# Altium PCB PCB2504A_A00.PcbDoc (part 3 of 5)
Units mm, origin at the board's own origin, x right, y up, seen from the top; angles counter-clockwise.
Board outline 115 x 60 mm, 6 copper layers (Top Layer, Signal Layer 2, Signal Layer 3, Signal Layer 4, Signal Layer 5, Bottom Layer), stack 1.555 mm thick; 403 components, 294 nets, 1344 pads, 774 vias.
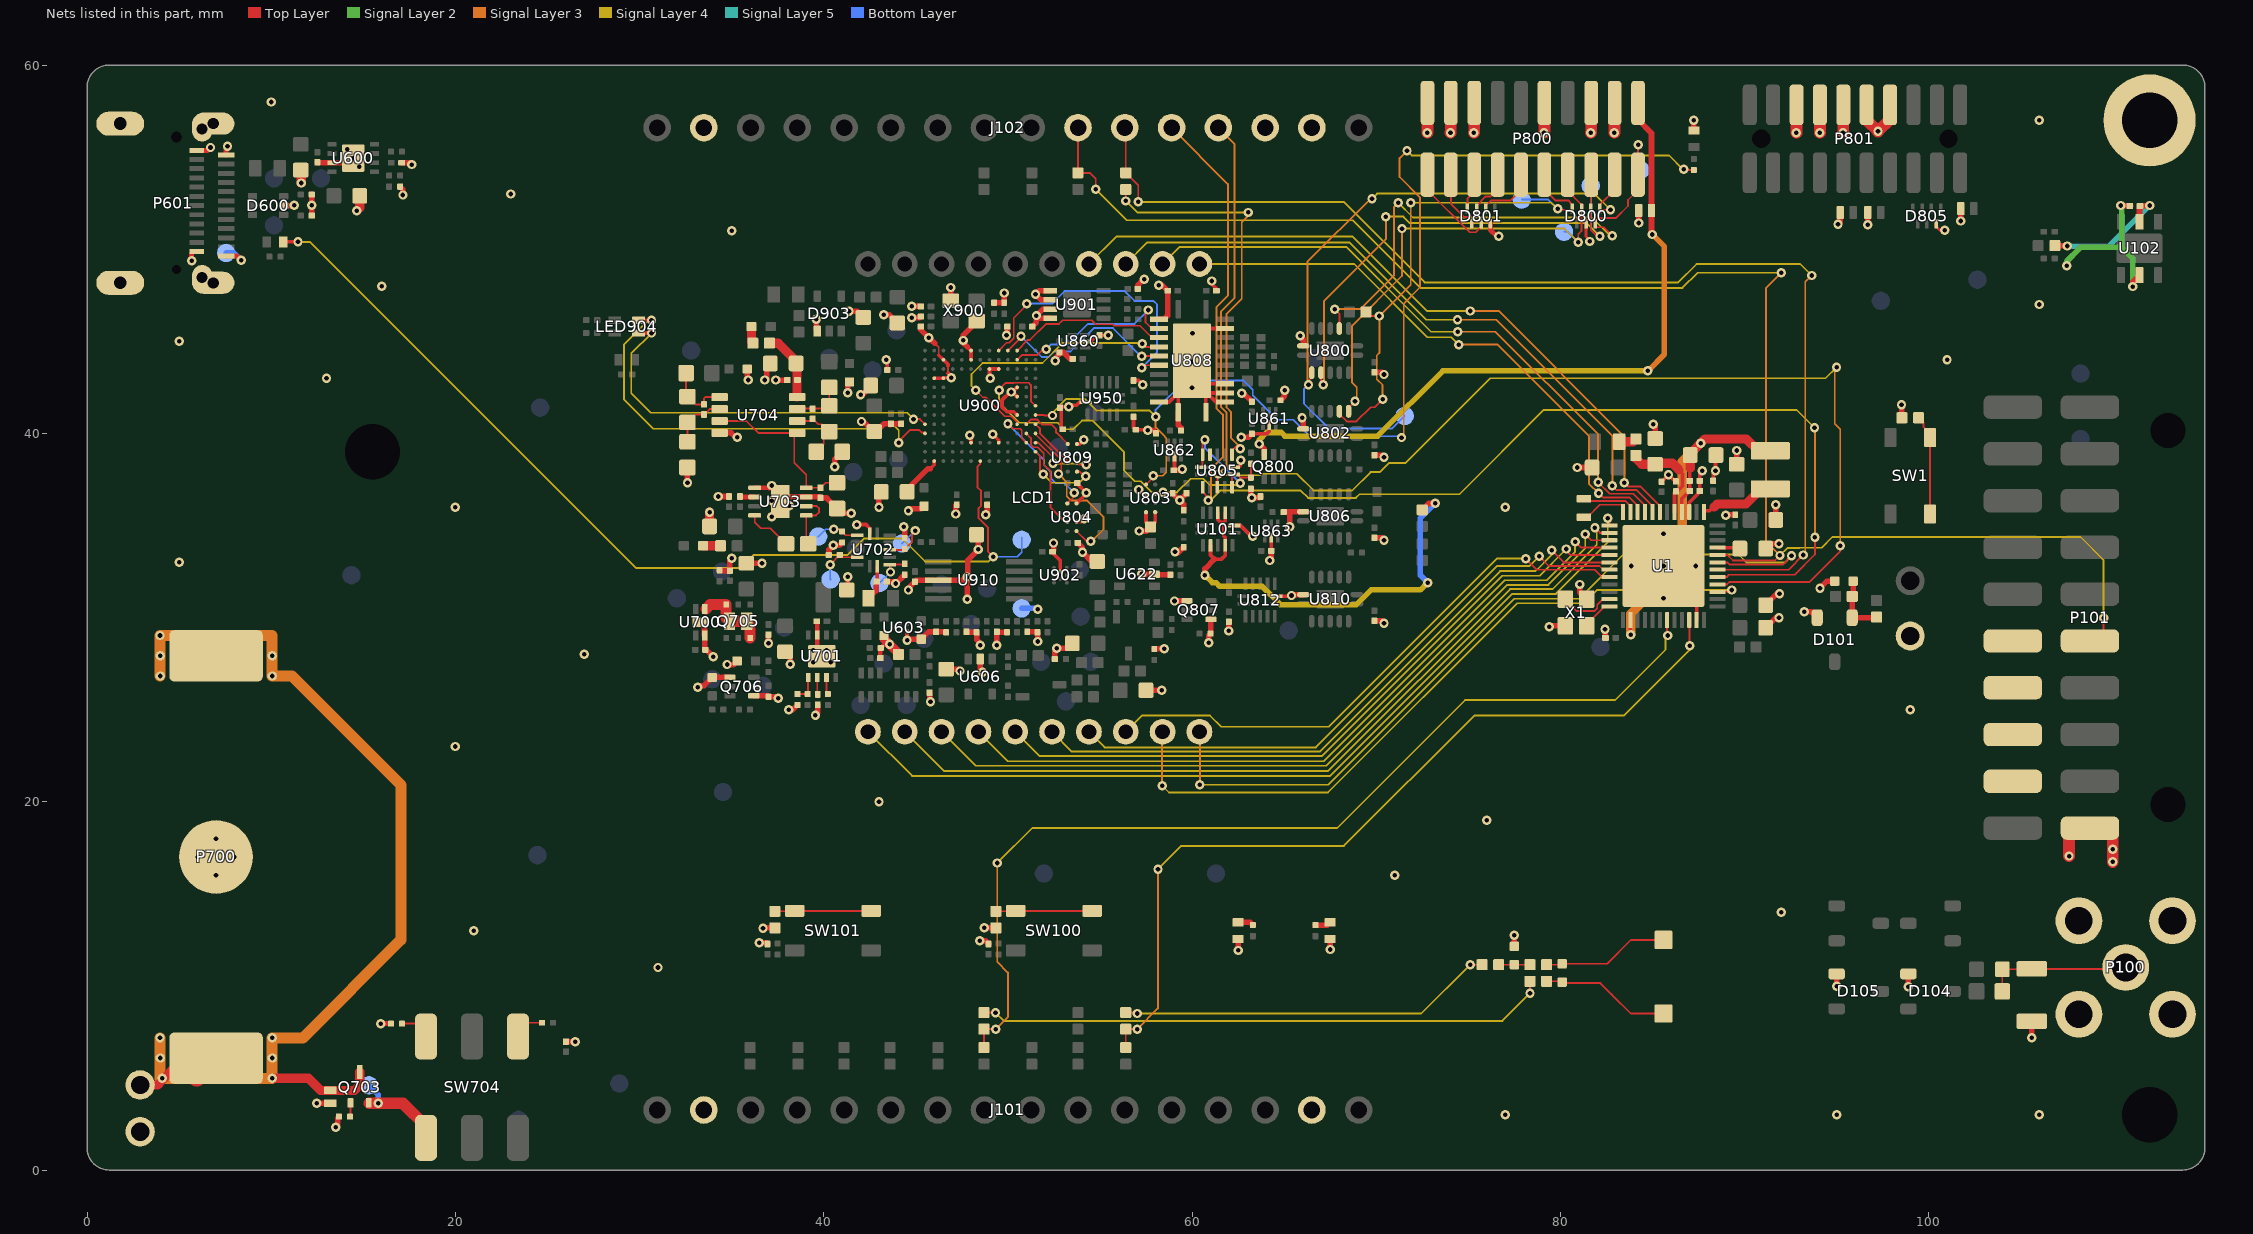
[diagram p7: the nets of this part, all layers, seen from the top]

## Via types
v1: diameter 0.508, hole 0.25, Top Layer to Bottom Layer, tented both sides, 774 vias

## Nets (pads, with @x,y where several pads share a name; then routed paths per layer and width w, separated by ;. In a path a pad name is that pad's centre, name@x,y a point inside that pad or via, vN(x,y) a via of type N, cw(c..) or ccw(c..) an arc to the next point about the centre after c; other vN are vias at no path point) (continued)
BREAKOUT_TOP10: J102.10 P101.9 R301.1 U1.32 | length 87.5
  Top Layer w0.1: J102.10@53.81,56.602 53.81,54.16 R301.1@53.8,54.15 54.45,54.15 54.775,53.825 v1(54.775,53.25) ; U1.32@88.535,33.4 89.075,33.4 89.375,33.1 91.65,33.1 v1(91.925,33.375) ; P101.9@108.76,28.73 109.205,28.73 109.5,29.025 v1(109.5,29.975)
  Signal Layer 3 w0.1: v1(91.925,33.375) 91.175,34.125 91.175,47.9 v1(92,48.725)
  Signal Layer 4 w0.1: v1@54.775,53.375 v1(54.775,53.25) 56.45,51.575 68.725,51.575 72.4,47.9 86.626,47.9 87.451,48.725 v1(92,48.725) ; v1(91.925,33.375) 92.325,33.775 92.65,33.775 ; v1(109.5,29.975) 109.5,33.125 108.25,34.375 94.775,34.375 94.193,33.793 92.993,33.793 ; 92.65,33.775 92.975,33.775 92.993,33.793 ; 92.65,33.775 92.668,33.793 92.993,33.793
BREAKOUT_TOP11: J102.11 R300.1 U1.30 | length 63.7
  Top Layer w0.1: J102.11@56.35,56.602 56.4,56.552 R300.1@56.4,54.15 57.075,53.475 v1(57.075,52.575) ; U1.30@88.535,32.6 92.4,32.6 v1(93.2,33.4)
  Signal Layer 3 w0.1: v1(93.2,33.4) 93.3,33.5 93.3,48.225 v1(93.65,48.575)
  Signal Layer 4 w0.1: v1(57.075,52.575) 68.25,52.575 72.625,48.2 86.4,48.2 87.4,49.2 93.025,49.2 v1(93.65,48.575)
BREAKOUT_TOP12: J102.12 U1.29 U805.1 | length 71.4
  Top Layer w0.1: U805.1@60.575,37.085 60.575,36.825 60.885,36.515 v1(60.885,36.379) ; U1.29@88.535,32.2 89.025,32.2 89.15,32.325 92.725,32.325 93.825,33.425 v1(93.825,34.363)
  Signal Layer 3 w0.1: J102.12@58.89,56.602 61.95,53.542 61.95,47.475 61.325,46.85 61.325,41.375 61.675,41.025 61.675,38.7 61.025,38.05 61.025,36.519 v1(60.885,36.379) ; v1(93.8,40.3) 93.825,40.275 v1(93.825,34.363)
  Signal Layer 4 w0.1: v1(60.885,36.379) 61.007,36.379 61.521,36.893 65.907,36.893 66.3,36.5 68.894,36.5 69.094,36.7 74.525,36.7 79.1,41.275 92.825,41.275 v1(93.8,40.3)
BREAKOUT_TOP13: J102.13 U1.28 U805.3 | length 75
  Top Layer w0.1: U805.3@61.375,37.085 v1@61.375,37.65 ; U1.28@88.535,31.8 89.044,31.8 89.169,31.925 93.525,31.925 95.2,33.6 v1(95.2,33.9)
  Signal Layer 3 w0.1: v1(61.425,37.8) 61.875,38.25 61.875,41.125 61.575,41.425 61.575,46.625 62.3,47.35 62.3,55.732 J102.13@61.43,56.602 ; v1(95,43.6) 95,43.7 95.1,43.7 94.9,43.5 94.9,40.525 95.2,40.225 v1(95.2,33.9)
  Signal Layer 4 w0.1: v1(61.425,37.8) 61.5,37.725 63.675,37.725 63.757,37.807 65.693,37.807 66.6,36.9 68.7,36.9 69.7,37.9 70.2,37.9 70.7,38.4 71.6,38.4 76.2,43 94.4,43 v1(95,43.6)
BREAKOUT_TOP14: J102.14
DAC_LC_EXCITE: R121.1 R304.2 | length 20.5
  Top Layer w0.1: R304.2@56.4,8.55 56.975,8.55 v1(57.025,8.5) ; v1(75.1,11.15) R121.1@75.75,11.15
  Signal Layer 4 w0.1: v1(57.025,8.5) 72.45,8.5 v1(75.1,11.15)
DBG_VREGO: C902.1 U900.A12 | length 2.4
  Top Layer w0.1: C902.1@44.45,36.875 44.5,36.825 C902.1@44.525,36.825
  Top Layer w0.2: 45.788,38.088 46,38.3 U900.A12@46,38.5
  Top Layer w0.3: C902.1@44.45,36.875 45.663,38.088 45.788,38.088
DEBUG_#RESET_IN: U808.7 U900.N5 | length 15.7
  Top Layer w0.1: U900.N5@49.5,44.5 49.925,44.925 50.081,44.925 50.318,45.162 50.318,46.268 51.025,46.975 v1(51.025,47.05) ; v1(57.275,43.575) 57.275,43.6 57.375,43.7 U808.7@58.205,43.7
  Bottom Layer w0.1: v1(51.025,47.05) 52.4,47.05 53.075,47.725 56.35,47.725 56.875,47.2 57.9,47.2 58.1,47 58.1,44.4 v1(57.275,43.575)
DEBUG_DH_SW_ENABLE: R900.1 U803.A1 U900.F1 | length 60.3
  Top Layer w0.1: U900.F1@51.5,41 51.95,41 51.975,40.975 v1(52.425,40.975) ; U803.A1@57.5,37.225 v1@57.825,37.55 ; v1@86.7,54.3 R900.1@87.25,54.3
  Signal Layer 3 w0.1: v1(57.9,37.7) 58.4,37.7 58.6,37.9 58.6,39.75 58.425,39.925 58.025,40.325 v1(58.025,40.9) ; v1(71.375,39.775) 71.5,39.9 71.5,47.05 72.375,47.925 72.375,52.825 71.275,53.925 71.275,54.95 v1(71.675,55.35)
  Signal Layer 4 w0.1: v1(52.425,40.975) 52.425,41.131 53.169,41.875 54.175,41.875 54.8,41.25 57.675,41.25 v1(58.025,40.9) ; v1(71.675,55.35) 71.925,55.1 85.9,55.1 v1@86.65,54.35
  Bottom Layer w0.1: v1(58.025,40.9) 58.025,41.275 59.618,42.868 62.807,42.868 63.3,42.375 63.3,42.075 64.632,40.743 65.507,40.743 66.4,39.85 71.3,39.85 v1(71.375,39.775)
  other v1: 86.7,54.35
DEBUG_MCU_SW_ENABLE: R814.2 R815.2 U803.B2 U805.5 U805.6 U805.12 U805.13 U900.G1 | length 28.5
  Top Layer w0.1: v1(49.525,42.35) 49.525,42.4 49.857,42.732 50.288,42.732 50.306,42.75 51.125,42.75 51.25,42.625 51.25,41.75 U900.G1@51.5,41.5 ; U803.B2@58,36.725 58.425,36.725 v1(58.425,36.8) ; U805.13@60.49,38.17 60.575,38.255 U805.12@60.575,38.855 60.575,39.525 v1(60.7,39.65) ; U805.5@62.175,37.085 62.175,37.685 U805.6@62.26,37.77 62.48,37.77 62.65,37.6 ; v1(62.625,37.3) 62.625,37.575 62.65,37.6 ; R815.2@63.2,38.35 R814.2@63.2,37.6 62.65,37.6
  Signal Layer 4 w0.1: v1(49.525,42.35) 49.525,41.669 50.612,40.582 52.718,40.582 53.075,40.225 53.55,40.225 54.025,40.7 54.6,40.7 56.3,39 56.3,38 56.9,37.4 57.217,37.4 57.817,36.8 v1(58.425,36.8) ; v1@58.425,36.875 v1(58.425,36.8) ; v1(62.625,37.3) 62.525,37.2 60.961,37.2 60.618,37.543 59.918,37.543 59.175,36.8 v1(58.425,36.8)
  Bottom Layer w0.1: v1(60.7,39.65) 60.7,39.225 v1(62.625,37.3)
DEBUG_RESET_#OE: U804.A1 U900.D1 | length 9.4
  Top Layer w0.1: U900.D1@51.5,40 51.5,39.962 52.895,38.566 52.895,37.945 v1(52.75,37.8) ; U804.A1@53.725,34.7 54.275,34.15 v1(54.5,34.15)
  Signal Layer 3 w0.1: v1@52.825,37.8 v1(52.75,37.8) 53.2,37.35 53.2,36.6 53.45,36.35 54.306,36.35 55.2,35.456 55.2,34.8 54.55,34.15 v1(54.5,34.15)
DEBUG_TCK_SWCLK_#OE: U809.A1 U900.B1 | length 4.6
  Top Layer w0.1: U900.B1@51.5,39 51.75,38.75 51.75,37.954 v1(51.928,37.777) ; U809.A1@53.75,37.925 53.9,37.925 54.15,37.675 v1(54.225,37.675)
  Signal Layer 4 w0.1: v1(51.928,37.777) 52.379,37.325 53.875,37.325 v1(54.225,37.675)
DEBUG_TCK_SWCLK_IN: U808.4 U900.N3 | length 8.8
  Top Layer w0.1: U900.N3@50.5,44.5 51.075,45.075 51.2,45.075 52.075,45.95 52.775,45.95 52.975,46.15 54.55,46.15 54.775,45.925 55.694,45.925 55.769,45.85 57.175,45.85 57.825,45.2 U808.4@58.205,45.2
DEBUG_TCK_SWCLK_OUT: U809.B1 U900.C1 | length 4.1
  Top Layer w0.1: U900.C1@51.5,39.5 51.65,39.5 52.45,38.7 v1(52.45,38.375) ; v1@52.5,38.375 v1@52.5,38.5 ; U809.B1@53.75,38.425 53.775,38.4 53.875,38.3 v1(54.25,38.3)
  Signal Layer 4 w0.1: v1(52.45,38.375) 54.15,38.375 54.225,38.3 v1(54.25,38.3)
DEBUG_TDI_#OE: U809.B2 U900.E1 | length 2.8
  Top Layer w0.1: U900.E1@51.5,40.5 51.75,40.25 51.75,39.994 53.25,38.494 U809.B2@53.25,38.425
DEBUG_TDI_C2DPS: U805.11
DEBUG_TDI_IN: U808.6 U900.N4 | length 10.2
  Top Layer w0.1: U900.N4@50,44.5 v1@50.675,45.175 ; v1(57.275,44.2) U808.6@58.205,44.2
  Bottom Layer w0.1: v1(50.711,45.275) 51.836,44.15 52.219,44.15 52.519,44.45 53.4,44.45 54.668,45.718 55.707,45.718 57.225,44.2 v1(57.275,44.2)
DEBUG_TDI_OUT: U809.D2 U900.E2 | length 3
  Top Layer w0.1: U900.E2@51,40.5 51.25,40.75 51.604,40.75 51.871,40.482 52.374,40.482 52.618,40.238 52.618,40.057 52.645,40.03 52.645,40.026 53.246,39.425 U809.D2@53.25,39.425
DEBUG_TDO_SWO: R300.2 U805.8 | length 21.8
  Top Layer w0.1: v1(56.4,52.625) R300.2@56.4,53.25 ; U805.8@62.175,38.855 62.175,39.075 62.425,39.325 62.575,39.175 v1(62.625,39.175)
  Signal Layer 3 w0.1: v1(62.625,39.175) 62.625,39.25 62.125,39.75 62.125,41.158 61.875,41.408 61.875,46.491 62.7,47.316 62.7,51.475 v1@63.05,51.825
  Signal Layer 4 w0.1: v1(56.4,52.625) 57.025,52 v1(63.05,52)
DEBUG_TDO_SWO_IN: U808.5 U900.E3 | length 15.1
  Top Layer w0.1: v1(48.25,42.35) 48.65,41.95 48.82,41.95 49.838,40.932 50.175,40.932 50.5,40.607 U900.E3@50.5,40.5 ; v1(57.3,44.875) 57.325,44.875 57.5,44.7 U808.5@58.205,44.7
  Signal Layer 3 w0.1: v1(48.25,42.35) v1@48.331,42.35
  Signal Layer 4 w0.1: v1(48.25,42.35) 48.025,42.575 48.025,43.225 48.625,43.825 51.881,43.825 52.974,44.918 57.257,44.918 v1(57.3,44.875)
DEBUG_TMS_SWDIO_#OE: U804.B2 U900.D2 | length 5.9
  Top Layer w0.1: U900.D2@51,40 51.25,39.75 51.25,39.388 51.388,39.25 51.617,39.25 51.95,38.917 51.95,38.31 52.32,37.94 52.32,36.926 52.307,36.913 52.307,36.587 52.32,36.574 52.32,35.968 53.088,35.2 U804.B2@53.225,35.2
DEBUG_TMS_SWDIO_IN: U808.3 U900.M3 | length 9.8
  Top Layer w0.1: U900.M3@50.5,44 50.75,44.25 51.604,44.25 51.929,44.575 v1(52.075,44.575) ; v1(57.625,46.7) 57.475,46.55 57.475,46.025 57.8,45.7 U808.3@58.205,45.7
  Bottom Layer w0.1: v1(52.075,44.575) 52.325,44.825 53.225,44.825 54.35,45.95 56.875,45.95 v1(57.625,46.7)
DEBUG_TMS_SWDIO_OUT: U804.D2 U900.C2 | length 7.8
  Top Layer w0.1: v1@50.1,40.45 50.3,40.25 50.675,40.25 50.75,40.175 50.75,39.75 U900.C2@51,39.5 ; U804.D2@53.225,36.2 53.6,36.575 v1(53.6,36.775)
  Bottom Layer w0.1: v1(50.002,40.527) 51.95,38.579 51.95,38.31 52.357,37.903 52.357,37.543 52.6,37.3 53.075,37.3 v1(53.6,36.775)
DEBUG_TRACECLK: D801.2 P800.12 | length 3.2
  Top Layer w0.1: D801.2@75.95,52.215 75.95,52.35 76.25,52.65 77.3,52.65 77.865,53.215 P800.12@77.865,54.05
DEBUG_TRACED0: D801.3 P800.14 | length 2.5
  Top Layer w0.1: D801.3@75.45,52.215 75.45,52.375 75.95,52.875 76.225,52.875 76.595,53.245 P800.14@76.595,54.05
DEBUG_TRACED1: D801.4 P800.16 | length 2
  Top Layer w0.1: D801.4@74.95,52.215 74.95,52.75 75.325,53.125 P800.16@75.325,54.05
DEBUG_TRACED2: D801.5 P800.18 | length 3.3
  Top Layer w0.1: P800.18@74.055,54.05 74.055,52.47 74.775,51.75 75,51.75 75.2,51.55 D801.5@75.2,51.385
DEBUG_TRACED3: D801.6 P800.20 | length 5
  Top Layer w0.1: P800.20@72.785,54.05 72.785,53.215 75.075,50.925 75.4,50.925 75.7,51.225 D801.6@75.7,51.385
DH_#RESET: D800.4 P800.10 R816.1 TPJ811.1 U802.3 | length 29.6
  Top Layer w0.1: U802.3@68,41.2 68,41.05 68.4,40.65 68.925,40.65 69.7,41.425 69.925,41.425 v1(70.35,41.85) ; R816.1@69.45,46.6 69.675,46.375 v1(70.175,46.375) ; P800.10@79.135,54.05 79.135,53.24 79.725,52.65 80.425,52.65 80.65,52.425 D800.4@80.65,52.215 80.585,52.15 79.85,52.15 v1(79.85,52.193)
  Signal Layer 3 w0.1: v1(70.35,41.85) 70.343,41.857 70.343,42.638 70.032,42.949 70.032,44.232 70.175,44.375 v1(70.175,46.375) 71.875,48.075 v1(71.875,52.525)
  Signal Layer 4 w0.1: v1(71.875,52.525) 79.518,52.525 v1(79.85,52.193)
  Bottom Layer w0.1: TPJ811.1@77.9,52.7 79.343,52.7 v1(79.85,52.193)
DH_TCK_SWCLK: D800.1 P800.4 TPJ818.1 U800.9 | length 35.8
  Top Layer w0.1: v1(66.325,42.65) 66.325,42.85 66.5,43.025 U800.9@66.5,43.3 ; v1(82.725,52.15) 82.215,52.15 D800.1@82.15,52.215 82.15,52.425 82.945,53.22 P800.4@82.945,54.05
  Signal Layer 3 w0.1: v1@66.268,42.793 66.268,49.318 69.7,52.75 v1(69.775,52.75)
  Signal Layer 4 w0.1: v1(69.775,52.75) 70.05,53.025 81.85,53.025 v1(82.725,52.15)
  Bottom Layer w0.1: v1(66.325,42.65) 66.075,42.4 66.075,41.625 67.425,40.275 70.875,40.275 TPJ818.1@71.55,40.95
DH_TDI: D800.3 P800.8 TPJ820.1 U802.2 | length 26.3
  Top Layer w0.1: U802.2@68.5,41.2 68.5,41.4 v1(68.85,41.75) ; P800.8@80.405,54.05 80.405,53.17 81.15,52.425 D800.3@81.15,52.215 81.15,51 80.975,50.825 v1(80.975,50.375)
  Signal Layer 3 w0.1: v1(68.85,41.75) 68.943,41.843 68.943,42.513 68.89,42.565 68.682,42.774 68.682,45.832 71.4,48.55 v1(71.4,51.125)
  Signal Layer 4 w0.1: v1(71.4,51.125) 80.225,51.125 v1(80.975,50.375)
  Bottom Layer w0.1: TPJ820.1@80.2,50.95 80.4,50.95 v1(80.975,50.375)
DH_TDO_SWO: D800.2 P800.6 TPJ812.1 U800.10 | length 29.8
  Top Layer w0.1: v1@67,42.725 U800.10@67,43.3 ; P800.6@81.675,54.05 81.65,54.025 D800.2@81.65,52.215 81.65,51.05 82,50.7 v1(82.15,50.7)
  Signal Layer 3 w0.1: v1(67.125,42.65) 67.168,42.693 67.168,47.193 70.525,50.55 v1(70.525,51.775)
  Signal Layer 4 w0.1: v1(70.525,51.775) 71.475,51.775 71.825,51.425 81.425,51.425 v1(82.15,50.7)
  Bottom Layer w0.1: TPJ812.1@81.65,53.45 81.65,51.2 v1(82.15,50.7)
DH_TMS_SWDIO: D800.7 P800.2 TPJ814.1 U800.3 | length 29.9
  Top Layer w0.1: v1(67.75,46.75) 68,46.5 U800.3@68,45.7 ; v1(82.825,50.725) 82.35,51.2 81.925,51.2 81.9,51.225 D800.7@81.9,51.385 81.9,51.525 82.075,51.7 83.025,51.7 83.675,52.35 83.675,52.675 84.215,53.215 P800.2@84.215,54.05 84.215,55.665 v1(84.225,55.675)
  Signal Layer 3 w0.1: v1(67.75,46.75) 69.125,46.75 70.975,48.6 70.975,52.3 v1(71.2,52.525)
  Signal Layer 4 w0.1: v1(71.2,52.525) 72,51.725 81.7,51.725 v1@82.7,50.725
  Bottom Layer w0.1: v1(84.225,55.675) 84.225,54.425 TPJ814.1@84.35,54.3
DH_VTREF: D809.1 P800.1 Q800.3 | length 39.2
  Top Layer w0.3: v1(63.65,39.425) 63.925,39.15 Q800.3@63.925,38.85 ; P800.1@84.215,57.95 84.215,57.035 84.95,56.3 84.95,52.2 D809.1@85,52.15 ; D809.1@84.95,52.1 84.95,50.85 v1(85,50.8)
  Signal Layer 3 w0.3: v1(84.75,43.4) 85.65,44.3 85.65,50.15 v1(85,50.8)
  Signal Layer 4 w0.3: v1(63.65,39.425) 63.65,39.65 64.05,40.05 64.853,40.05 65.046,39.857 65.093,39.857 65.1,39.85 70.075,39.85 73.625,43.4 v1(84.75,43.4)
EXP_HEADER4: P101.4
EXP_HEADER6: P101.6
EXP_HEADER8: P101.8
EXP_HEADER10: P101.10
GND: C3.2 C4.2 C5.2 C6.2 C8.2 C9.2 C10.2 C12.2 C13.2 C14.2 C15.2 C16.2 C40.2 C102.2 C103.2 C110.2 C113.2 C115.2 C117.2 C123.2 C130.2 C600.2 C602.2 C607.2 C608.2 C609.2 C610.2 C611.2 C621.2 C625.2 C632.2 C635.2 C638.2 C641.2 C652.2 C653.2 C655.2 C660.2 C700.2 C701.2 C702.2 C703.2 C705.2 C706.2 C707.2 C708.2 C709.2 C714.2 C720.2 C724.2 C728.2 C729.2 C730.2 C731.2 C747.2 C761.2 C762.2 C800.2 C803.2 C804.2 C805.2 C806.2 C807.2 C808.2 C809.2 C810.2 C827.2 C828.2 C860.2 C861.2 C862.2 C863.2 C864.2 C865.2 C866.2 C867.2 C900.2 C901.2 C902.2 C903.2 C904.2 C905.2 C906.2 C907.2 C908.2 C909.2 C910.2 C911.2 C914.2 C919.2 C921.2 C922.2 C924.2 C925.2 C926.2 C927.2 C950.2 C951.2 D101.2 D104.1 D105.1 D600.2 D703.2 D800.6 D801.7 D805.7 D806.2 D807.2 D808.2 D809.2 D903.1 J101.2 J101.15 J102.2 J102.15 LED100.2 LED101.2 LED900.2 M1.1 P100.2 P100.3 P100.4 P100.5 P101.1 P601.25@1.8,56.82 P601.26@1.8,48.18 P601.27@6.25,56.525 P601.27@6.85,56.82 P601.28@6.25,48.475 P601.28@6.85,48.18 P601.A1 P601.A12 P601.B1 P601.B12 P700.2 P800.3 P800.5 P800.9 P800.15 P800.17 P800.19 P801.7 P801.9 P801.11 P801.13 P801.15 Q706.1 Q706.4 Q807.1 Q807.4 R7.1 R104.2 R105.2 R112.2 R120.1 R602.1 R620.1 R621.1 R623.1 R628.2 R631.1 R634.1 R637.1 R640.1 R674.2 R688.2 R691.2 R703.1 R705.1 R706.1 R707.1 R708.1 R718.1 R754.1 R760.1 R763.1 R767.1 R771.1 R792.1 R794.2 R814.1 R839.1 R850.1 R851.1 R852.1 R853.1 R930.2 R931.2 R950.2 R981.2 ST701.1 TPH100.1 TPJ614.1 TPJ913.1 U1.0 U1.23 U1.39 U101.7 U102.2 U600.3 U600.9 U603.A1 U606.2 U622.2 U700.2 U700.5 U701.3 U701.9 U702.7 U703.3 U703.5 U703.9 U704.4 U800.7 U802.7 U803.B1 U803.D1 U803.D2 U804.B1 U804.D1 U805.7 U806.7 U808.2 U808.11 U808.12 U808.13 U808.14 U808.15 U808.16 U808.22 U808.25 U809.D1 U810.7 U812.7 U860.2 U861.2 U862.2 U863.2 U900.C5 U900.C8 U900.F3 U900.H3 U900.J3 U900.K11 U900.K12 U900.L5 U900.L6 U900.M8 U900.M11 U900.N8 U901.1 U901.2 U901.3 U901.4 U902.B2 U910.3 U950.7 X1.2 X1.4 X900.2 X900.4 | length 216.1
  Top Layer w0.1: 46.025,44.9 46.25,44.675 46.25,44.25 ; 46.75,43.275 46.75,43.674
  Top Layer w0.15: D800.6@81.4,51.385 81.4,50.7 81.6,50.5 v1(81.6,50.425) ; D805.7@100.4,51.385 100.4,51.25 100.6,51.05 v1@101.05,51.05
  Top Layer w0.2: v1(41.8,35.05) 42.3,35.05 42.5,34.85 U702.7@42.5,34.56 ; C900.2@42.55,42.6 C900.2@42.6,42.6 ; v1@43.3,44 v1@43.4,43.9 ; v1(43.4,44) v1@43.4,43.9 ; R763.1@43.45,43.45 43.45,43.85 v1@43.4,43.9 ; v1(44.525,28.775) 44.525,29.225 U603.A1@44.55,29.25 ; U900.K12@46,43 U900.K11@46.5,43 46.525,43.025 v1(46.925,43.025) 46.925,43.1 46.75,43.275 ; 46.25,44.25 U900.M11@46.5,44 46.75,43.75 46.75,43.674 ; 47.785,44.71 47.995,44.5 U900.N8@48,44.5 U900.M8@48,44 ; v1(47.925,39.9) 47.925,39.875 48,39.8 U900.C8@48,39.5 ; v1(49.05,43) 49,43.05 U900.L6@49,43.5 U900.L5@49.5,43.5 ; v1(49.172,39.954) 49.5,39.626 U900.C5@49.5,39.5 ; U900.F3@50.5,41 50.318,41.182 49.942,41.182 49.682,41.442 49.682,41.808 50.124,42.25 v1(50.175,42.25) 50.2,42.25 v1@50.225,42.275 ; U900.H3@50.5,42 v1@50.225,42.275 ; U900.J3@50.5,42.5 50.275,42.275 v1@50.225,42.275 ; C914.2@52.425,33.575 52.425,33.525 52.85,33.1 U902.B2@52.85,32.5 ; C911.2@52.825,41.375 C911.2@52.893,41.375 ; C909.2@52.975,40.225 52.893,40.307 C911.2@52.893,41.375 ; v1@53.25,41.5 v1@53.25,41.45 ; U804.B1@53.725,35.2 53.975,35.2 v1(54.15,35.375) ; U804.D1@53.725,36.2 54.25,36.725 v1(54.25,36.775) 53.775,37.25 C810.2@53.775,37.3 ; U809.D1@53.75,39.425 53.9,39.425 v1(54.125,39.65) ; U860.2@54.2,45 54.525,45 54.85,45.325 C862.2@54.975,45.325 v1(55.45,45.325) ; U950.7@54.24,41.7 53.9,41.7 53.73,41.53 53.38,41.53 v1(53.3,41.45) ; C950.2@56.825,42.875 57.1,42.875 v1(57.325,42.65) ; R950.2@56.85,40.925 56.825,40.9 56.825,40.325 R981.2@56.95,40.2 57.575,40.2 v1(57.6,40.175) ; v1(57.104,36.958) 57.104,36.996 57.1,37 57.1,36.95 57.325,36.725 U803.B1@57.5,36.725 ; U803.D1@57.5,35.725 57.5,35.175 R691.2@57.75,34.925 58,35.175 U803.D2@58,35.725 ; U808.11@58.205,41.7 58.75,41.7 U808.25@59.25,42.2 ; C860.2@59,38 59.05,38.05 U862.2@59.05,38.75 ; U808.12@59.25,41.155 U808.25@59.25,42.2 ; v1(60.025,45.45) 60.275,45.7 U808.22@61.795,45.7 ; U808.13@60.75,41.155 U808.25@60.75,42.2 ; v1(61.075,48.275) 61.075,48.1 61.325,47.85 C806.2@61.325,47.75 ; U808.14@61.795,41.7 61.3,41.7 U808.25@60.8,42.2 ; U808.15@61.795,42.2 U808.25@60.8,42.2 ; U808.16@61.795,42.7 60.225,42.7 v1(60,42.475) ; U805.7@62.26,38.17 62.52,38.17 62.625,38.275 62.625,38.525 v1(62.65,38.55) ; U101.7@62.285,35 U101.7@62.625,35 ; 62.65,35 U101.7@62.625,35 ; C864.2@63.25,39.975 64.05,39.975 64.2,40.125 U861.2@64.2,40.45 ; v1(63.3,34.425) 63.2,34.425 U101.7@62.625,35 ; C866.2@64.3,33.625 U863.2@64.3,34.35 ; U812.7@64.585,31.15 65.35,31.15 v1(65.4,31.2) ; C6.2@85.5,37.375 85.825,37.7 v1(85.875,37.75) 86.225,37.4 C4.2@86.275,37.4 ; v1(85.6,32.8) 87.4,31 U1.23@87.4,29.865 ; U1.39@87,35.735 87,36.25 87.575,36.825 C13.2@87.575,36.875 C14.2@87.575,37.425 87.575,37.85 v1(87.7,37.975) ; C9.2@88.3,37.425 88.3,37.85 v1(88.425,37.975) C12.2@88.425,38.85 ; C911.2@52.893,41.375 52.968,41.45 v1@53.25,41.45 ; v1@53.25,41.45 53.25,41.399 v1(53.3,41.45) ; v1@53.25,41.45 v1(53.3,41.45) ; U808.25@59.25,42.2 59.525,42.475 v1(60,42.475) ; v1(60,42.475) 60.275,42.2 U808.25@60.75,42.2 ; U808.25@60.75,42.2 U808.25@60.8,42.2
  Top Layer w0.25: U703.5@36.25,37.05 v1@37.05,37.05 ; C702.2@39.625,29.8 39.65,29.775 U701.3@39.65,29.05 39.65,28.15 U701.9@39.9,27.9 ; C703.2@41.25,31.5 41.3,31.55 v1(41.3,32.225) ; C610.2@43.075,27.8 43.075,28.325 R623.1@43.1,28.35 43.3,28.55 v1(43.575,28.55)
  Top Layer w0.27: v1(5.675,49.375) 5.675,49.775 5.775,49.875 P601.B1@5.95,49.875 ; P601.B12@5.95,55.375 6.55,55.375 v1(6.7,55.525) ; P601.A12@7.55,49.625 8.15,49.625 v1(8.375,49.4) ; P601.A1@7.55,55.125 7.55,55.5 7.625,55.575 v1(7.625,55.6) ; v1(15.95,7.95) R794.2@16.5,7.95 ; D801.7@76.2,51.385 76.2,51.05 76.55,50.7 v1(76.65,50.7)
  Top Layer w0.3: D600.2@10.675,52.375 11.225,52.375 v1(11.25,52.4) ; R621.1@12.2,51.825 12.2,51.9 v1(12.2,52.4) 12.2,52.9 R620.1@12.2,52.975 ; v1(12.475,3.625) D703.2@13.2,3.625 ; C600.2@12.5,54.725 12.525,54.7 U600.3@13.3,54.7 U600.9@14.2,54.7 ; v1(13.501,2.325) 13.6,2.424 13.6,2.825 R792.1@13.675,2.9 ; R602.1@17,53.4 17.15,53.25 v1(17.15,52.95) ; C602.2@17.075,54.7 17.525,54.7 v1(17.625,54.6) ; C706.2@26,6.975 v1(26.5,6.975) ; v1(32.6,37.325) R767.1@32.6,38.15 ; v1@33.152,26.227 33.225,26.3 33.5,26.3 C709.2@33.95,26.75 Q706.4@34.9,26.75 ; U700.5@33.3,29.75 33.525,29.75 33.525,29.05 U700.2@33.55,29.025 33.55,28.275 C708.2@33.575,28.25 33.625,28.25 v1(34,27.875) ; v1(34.275,36.575) C728.2@34.85,36.575 ; U704.4@34.345,40.025 34.975,40.025 35.2,39.8 v1(35.3,39.8) ; R760.1@34.35,32.575 34.375,32.55 C701.2@34.9,32.55 34.9,33.05 35,33.15 v1(35,33.225) ; v1(34.75,27.45) 35.1,27.45 C747.2@35.3,27.65 ; C700.2@35.8,32.95 v1(36.65,32.95) ; C720.2@35.85,43.5 35.85,42.95 v1(35.9,42.9) ; Q706.1@36.2,25.75 36.95,25.75 R754.1@37,25.7 37.425,25.7 37.5,25.625 v1(37.525,25.625) ; v1(36.5,12.35) 36.875,12.35 C103.2@36.95,12.275 ; v1(36.7,13.125) 36.725,13.15 R105.2@37.35,13.15 ; v1(36.8,42.9) 36.9,43 36.9,43.6 C731.2@37.1,43.8 ; v1(37,28.6) 37,28.625 C762.2@37,29.075 ; v1@37.05,37.05 v1(37.175,37.175) ; v1(37.4,42.9) C730.2@38.025,42.9 ; U703.9@37.65,36.025 37.7,36.075 U703.9@37.875,36.075 ; C761.2@37.9,28.15 38.175,27.875 v1(38.175,27.475) ; v1(38.1,25) 38.325,25 R703.1@38.575,25.25 ; v1(38.125,36.075) U703.9@37.875,36.075 ; v1(39.55,24.7) 39.675,24.825 C705.2@39.675,25.275 ; v1(39.6,46.2) 39.6,45.6 D903.1@39.65,45.55 ; R705.1@40.275,33.4 40.275,33.675 v1(40.525,33.925) 40.85,33.925 R706.1@41,34.075 ; v1(40.6,38.2) 40.6,38.6 R771.1@41,39 ; R718.1@40.725,36.093 R718.1@40.725,35.925 ; v1(41.3,42.2) 41.3,42.7 C724.2@41.4,42.8 ; v1(41.375,46.625) 41.825,46.625 C919.2@42.15,46.3 ; v1(41.5,35.675) 40.975,35.675 R718.1@40.725,35.925 ; v1(42,42.1) 42.1,42.1 C900.2@42.55,42.55 ; v1(42.05,40.65) 42.15,40.65 C907.2@42.75,40.05 ; C907.2@42.75,40 43.275,40.525 C924.2@43.65,40.525 ; v1(43,36) C902.2@43,36.95 ; v1@43.3,46.45 43.55,46.45 C903.2@44,46 ; C707.2@43.425,31.95 43.8,31.95 v1(43.9,31.85) 43.925,31.85 R708.1@44.4,32.325 ; C924.2@43.6,40.475 C924.2@43.65,40.525 ; C925.2@44.2,40.525 C924.2@43.65,40.525 ; v1(44.35,34.925) 44.4,34.875 R707.1@44.4,34.325 ; v1(44.525,28.775) 44.575,28.825 C608.2@45.3,28.825 45.7,29.225 C638.2@46.1,29.225 46.625,29.225 R637.1@46.65,29.2 ; v1(44.6,31.5) 44.6,31.6 C922.2@44.95,31.95 45.025,32.025 U910.3@46.225,32.025 47.625,32.025 v1(47.8,32.2) ; v1(44.6,35.8) 44.7,35.9 45.3,35.9 C901.2@45.45,36.05 ; v1(44.775,46.275) 45.2,46.275 C905.2@45.275,46.35 ; v1(44.775,46.9) C906.2@45.275,46.9 ; C904.2@45.275,45.8 45.275,45.625 v1(45.7,45.2) ; v1@45.7,45.15 v1(45.7,45.2) ; C621.2@45.75,25.925 45.75,25.475 v1(45.8,25.425) ; 46.025,44.9 45.925,45 45.9,45 v1(45.7,45.2) ; C660.2@46.65,27.2 47.3,27.2 v1(47.4,27.1) ; X900.4@46.9,47.2 v1@46.9,47.9 ; v1(47.175,35.625) C927.2@47.175,36.075 ; v1@47.575,45.05 47.575,45.325 48.3,46.051 X900.2@48.3,46.1 ; v1(47.575,45.05) 47.575,44.92 47.785,44.71 ; C641.2@47.75,29.225 47.775,29.2 R640.1@48.3,29.2 48.3,28.8 48.5,28.6 v1(48.5,28.5) ; v1(47.8,31) v1(47.8,32.2) ; C921.2@48.3,34.5 48.4,34.4 v1(48.4,33.7) 47.825,33.125 47.825,32.225 v1(47.8,32.2) ; v1(48.475,12.45) 48.775,12.45 C102.2@48.95,12.275 ; U606.2@48.5,27.75 48.5,27.15 v1(48.625,27.025) ; v1(48.725,13.15) R104.2@49.35,13.15 ; v1(48.8,35.575) 48.875,35.65 C926.2@48.875,36.125 ; R931.2@49.25,47.1 R930.2@49.8,47.1 v1@49.8,47.575 ; v1(49.4,28.5) 49.4,28.725 C635.2@49.4,29.225 49.425,29.2 R634.1@49.95,29.2 ; v1@49.975,45.425 C910.2@49.975,45.8 ; C632.2@51.05,29.225 51.575,29.225 R631.1@51.6,29.2 51.625,29.175 v1(51.625,28.7) ; C908.2@51.325,45.8 51.55,46.025 v1(51.55,46.4) ; U901.4@52.3,46.25 51.7,46.25 v1(51.55,46.4) ; U901.3@52.3,46.75 51.9,46.75 v1(51.55,46.4) ; U901.2@52.3,47.25 51.8,47.25 v1(51.5,47.55) 51.7,47.75 U901.1@52.3,47.75 ; C914.2@52.425,33.575 52.5,33.65 52.5,34.025 v1(52.475,34.05) ; R674.2@52.55,27.75 52.55,28.225 v1(52.65,28.325) 53.225,28.325 C625.2@53.5,28.6 ; v1(52.575,43.95) 52.575,44.095 52.768,44.288 52.768,44.368 R850.1@52.8,44.4 53.033,44.4 53.383,44.05 C863.2@53.525,44.05 ; C804.2@53.8,34.05 54.05,33.8 v1(54.05,33.55) 54.55,33.05 C652.2@54.85,33.05 ; C951.2@57.05,47.85 57.05,48.025 v1(57.4,48.375) ; v1(57.125,34.7) 57.525,34.7 R691.2@57.75,34.925 ; v1(57.275,32.375) 57.3,32.35 U622.2@57.95,32.35 57.975,32.325 C653.2@58.825,32.325 ; C655.2@57.5,26.05 v1(58.35,26.05) ; v1(57.6,40.175) 57.875,40.175 C861.2@58.05,40 ; R688.2@57.95,28.3 v1(58.5,28.3) ; v1(58.2,48.05) 58.375,48.05 C808.2@58.675,47.75 58.675,46.4 58.475,46.2 U808.2@58.205,46.2 ; C807.2@58.95,36.75 v1(59.325,36.375) ; C860.2@59,38 59.425,38 v1(59.475,38.05) ; v1(59.05,30.9) Q807.4@59.725,30.9 ; v1(59.075,33.575) 59.2,33.575 59.25,33.525 C113.2@59.55,33.825 ; U808.12@59.25,41.155 59.25,40.45 59.4,40.3 R852.1@59.4,40.15 ; R112.2@59.55,35.825 59.55,36.15 v1(59.325,36.375) ; C800.2@59.7,36.75 v1(59.325,36.375) ; v1(60.9,28.625) 60.9,29.025 R839.1@61,29.125 61.025,29.15 Q807.1@61.025,29.9 ; v1(62,29.275) C828.2@62,29.775 ; v1(62.5,11.925) 62.5,12.075 LED101.2@62.5,12.55 ; v1(62.675,39.8) 63.075,39.8 C864.2@63.25,39.975 ; v1(62.7,42.175) 62.8,42.175 C865.2@63.25,41.725 ; R814.1@63.2,37 63.2,36.625 63.25,36.575 v1(63.25,36.5) 63.65,36.5 C867.2@63.725,36.575 ; v1(64.225,33.1) 64.3,33.175 C866.2@64.3,33.625 ; R851.1@64.8,41.8 65.007,42.007 65.007,42.079 65.025,42.097 v1(65.025,42.35) ; R853.1@64.975,35.725 65,35.75 65.278,35.75 ; v1(65.3,34.925) 65.3,35.722 65.275,35.747 65.278,35.75 ; v1(65.4,31.2) 65.45,31.25 U810.7@66.05,31.25 ; v1(65.875,45.3) 66.05,45.125 U800.7@66.05,44.75 ; v1(65.975,40.85) 65.975,40.775 66.05,40.7 U802.7@66.05,40.25 ; U806.7@66.05,35.75 65.278,35.75 ; v1(67.5,11.975) 67.5,12.025 LED100.2@67.5,12.55 ; C827.2@69.9,29.825 70.3,29.825 v1(70.425,29.7) ; C809.2@69.9,34.325 70.3,34.325 v1(70.425,34.2) ; C805.2@69.9,38.825 70.3,38.825 v1(70.425,38.7) ; C803.2@69.9,43.325 70.3,43.325 v1(70.425,43.2) ; C123.2@77.5,12.15 v1(77.5,12.75) ; v1(79.4,29.5) 79.45,29.55 X1.2@80.275,29.55 ; v1(80.925,38.15) C5.2@81.725,38.15 ; v1(81.05,31.8) 81.05,31.375 X1.4@81.425,31 ; v1(82.425,29.375) 82.45,29.35 C8.2@82.45,28.9 ; v1(84.25,51.425) D809.2@84.25,52.1 ; v1(85.05,40.5) 85.15,40.4 C3.2@85.15,39.725 ; LED900.2@87.25,56.45 v1(87.25,57) ; v1(88.975,35.55) 89.05,35.55 89.075,35.575 C15.2@89.5,35.575 ; C10.2@89.575,38.325 v1(89.575,39.075) ; C130.2@91.15,29.45 91.7,30 v1(91.875,30) ; C117.2@91.15,30.675 91.175,30.7 91.775,31.3 v1(91.9,31.3) v1@92,31.3 ; C40.2@91.15,33.75 91.225,33.75 91.475,34 v1(91.875,34) ; C16.2@91.7,35.3 91.7,36.05 v1(91.7,36.125) ; v1(93.25,30.325) 93.625,30.325 D101.2@93.95,30 ; v1(94.1,31.6) 94.475,31.975 C115.2@94.9,31.975 ; v1(95,9.975) D105.1@95,10.65 ; v1(95.075,51.35) 95.2,51.475 D806.2@95.2,52 ; v1(96.7,51.325) D807.2@96.7,52 ; v1(98.525,41.55) 98.55,41.525 R7.1@98.55,40.85 ; v1(98.9,9.95) D104.1@98.9,10.65 ; v1(101.75,51.534) D808.2@101.75,52.209 ; v1(105.6,7.175) R120.1@105.6,8.075 ; v1@110.475,52.375 C110.2@110.975,52.375 ; v1(111.075,47.975) 111.075,48.225 U102.2@111.45,48.6 ; U703.9@37.875,36.075 U703.9@37.65,36.3 37.9,36.55 U703.3@39.05,36.55 39.775,36.55 C729.2@39.825,36.5 40.15,36.5 R718.1@40.725,35.925 ; C927.2@47.175,36.075 47.175,36.1 47.2,36.125 C927.2@47.225,36.125 C927.2@47.175,36.075
  Top Layer w0.5: C611.2@11.6,54.3 11.5,54.3 11.625,54.175 v1(11.625,53.6) ; v1(14.65,52.1) 14.8,52.25 C607.2@14.8,52.9 ; C714.2@33.8,34.95 v1(33.8,35.725) ; C609.2@43.275,29.025 43.275,28.85 v1(43.575,28.55) 44.05,28.075 R628.2@44.05,28
  Top Layer w0.635: v1(72.765,56.325) 72.785,56.345 P800.19@72.785,57.95 ; v1(74.035,56.325) 74.055,56.345 P800.17@74.055,57.95 ; v1(75.305,56.325) 75.325,56.345 P800.15@75.325,57.95 ; v1(79.115,56.325) 79.135,56.345 P800.9@79.135,57.95 ; v1(81.655,56.325) 81.675,56.345 P800.5@81.675,57.95 ; v1(82.925,56.325) 82.945,56.345 P800.3@82.945,57.95 ; v1(92.81,56.325) 92.835,56.325 92.825,56.335 P801.15@92.825,57.841 ; v1(94.08,56.325) 94.105,56.325 94.095,56.335 P801.13@94.095,57.841 ; v1(95.35,56.325) 95.375,56.325 95.365,56.335 P801.11@95.365,57.841 ; P801.9@96.635,57.841 96.635,57.015 v1(97.25,56.4) 97.905,57.055 P801.7@97.905,57.841 ; v1(107.625,17.05) 107.625,18.25 107.945,18.57 P101.1@108.76,18.57 109.705,18.57 110,18.275 v1(110,17.425) v1(110,16.75) v1@110,16.725
  Signal Layer 2 w0.3: v1(107.505,49.102) 107.5,49.108 107.5,49.35 108.25,50.1 110.475,50.1 ; v1@110.475,52.375 110.475,50.1 ; v1(111.075,47.975) 111.075,49.5 110.475,50.1
  Signal Layer 3 w0.2: v1@49.15,39.9 49.172,39.922 v1(49.172,39.954)
  Signal Layer 3 w0.3: v1(33.152,26.226) v1@33.175,26.25 ; v1(65.975,40.85) v1@65.975,40.9
  Bottom Layer w0.3: TPJ614.1@7.55,49.8 7.975,49.8 v1(8.375,49.4) ; TPJ913.1@50.751,30.501 51.651,30.501 51.625,30.475 v1(51.625,30.45)
  other v1: 77,3 95,3 106,3 31,11 21,13 92,14 7,16 71,16 6,17 8,17 7,18 76,19 43,20 20,23 99,25 39.425,27.575 40.375,27.575 27,28 39.425,28.225 40.15,28.225 85.6,31.05 83.85,32.8 87.35,32.8 5,33 85.6,34.55 37.175,35.475 20,36 77,36 37.175,36.35 13,43 60,43.9 101,44 5,45 49.925,45.325 43.25,46.45 106,47 49.8,47.625 46.9,47.925 16,48 35,51 100.875,51.025 110.425,52.375 23,53 14.775,54.475 14.45,54.95 14.125,55.425 106,57 10,58
HFXTAL_I: U1.11 X1.1 | length 3.1
  Top Layer w0.1: X1.1@80.275,31 80.275,30.975 80.9,30.35 81.85,30.35 82,30.5 82,30.7 82.3,31 U1.11@82.665,31
HFXTAL_O: U1.12 X1.3 | length 1.7
  Top Layer w0.1: X1.3@81.425,29.55 81.425,29.642 82.383,30.6 U1.12@82.665,30.6
LCD_A0: LCD1.9 U1.27 | length 39.6
  Top Layer w0.1: U1.27@88.535,31.4 v1@89.3,31.4 ; v1(89.3,31.5) v1@89.4,31.5
  Signal Layer 3 w0.1: v1(58.375,20.875) 58.375,23.425 58.575,23.625 LCD1.9@58.4,23.8
  Signal Layer 4 w0.1: v1(58.375,20.875) 58.75,20.5 67.375,20.5 77.65,30.775 81.275,30.775 82,31.5 v1(89.3,31.5)
LCD_A4: LCD1.10 U1.31 | length 44.8
  Top Layer w0.1: U1.31@88.535,33 89.075,33 89.2,32.875 92.075,32.875 v1(92.55,33.35)
  Signal Layer 3 w0.1: LCD1.10@60.4,23.8 60.45,23.75 60.425,23.725 v1(60.425,20.925)
  Signal Layer 4 w0.1: v1(60.425,20.925) 67.4,20.925 77.5,31.025 81.025,31.025 83.425,33.425 89.675,33.425 90.118,32.982 92.182,32.982 v1(92.55,33.35)
LCD_C0: LCD1.1 U1.1 | length 48.3
  Top Layer w0.1: v1(82.579,35.402) 82.665,35.316 U1.1@82.665,35
  Signal Layer 4 w0.1: LCD1.1@42.4,23.8 44.8,21.4 67.5,21.4 77.388,31.288 79.763,31.288 82.575,34.1 82.575,35.425 82.579,35.421 v1(82.579,35.402)
  Signal Layer 5 w0.1: v1(82.579,35.402) 82.579,35.429 v1@82.625,35.475
LCD_C1: LCD1.2 U1.2 | length 45.4
  Top Layer w0.1: v1(81.879,34.877) 82.156,34.6 U1.2@82.665,34.6
  Signal Layer 4 w0.1: LCD1.2@44.4,23.8 46.525,21.675 67.4,21.675 77.275,31.55 79.575,31.55 81.975,33.95 81.975,34.775 81.9,34.85 81.9,34.875 81.898,34.877 v1(81.879,34.877)
LCD_C2: LCD1.3 U1.3 | length 42.8
  Top Layer w0.1: v1(81.35,34.525) 81.675,34.2 U1.3@82.665,34.2
  Signal Layer 4 w0.1: LCD1.3@46.4,23.8 48.25,21.95 67.3,21.95 77.125,31.775 79.35,31.775 81.35,33.775 v1(81.35,34.525)
LCD_C3: LCD1.4 U1.4 | length 40.3
  Top Layer w0.1: v1(80.8,34.125) 81.125,33.8 U1.4@82.665,33.8
  Signal Layer 4 w0.1: LCD1.4@48.4,23.8 50,22.2 67.15,22.2 76.975,32.025 79.25,32.025 80.8,33.575 v1(80.8,34.125)
LCD_C4: LCD1.5 U1.5 | length 37.7
  Top Layer w0.1: v1(80.325,33.725) 80.325,33.625 80.55,33.4 U1.5@82.665,33.4
  Signal Layer 4 w0.1: LCD1.5@50.4,23.8 51.725,22.475 67.05,22.475 76.85,32.275 78.875,32.275 v1(80.325,33.725)
LCD_C5: LCD1.6 U1.6 | length 35.7
  Top Layer w0.1: v1(79.525,33.65) 80.175,33 U1.6@82.665,33
  Signal Layer 4 w0.1: LCD1.6@52.4,23.8 53.475,22.725 66.925,22.725 76.725,32.525 78.65,32.525 79.525,33.4 v1(79.525,33.65)
LCD_C6: LCD1.7 U1.7 | length 33.2
  Top Layer w0.1: v1(78.85,33.325) 79.375,32.8 82.126,32.8 82.326,32.6 U1.7@82.665,32.6
  Signal Layer 4 w0.1: LCD1.7@54.4,23.8 55.25,22.95 66.725,22.95 76.582,32.807 78.332,32.807 v1(78.85,33.325)
LCD_C7: LCD1.8 U1.8 | length 31.1
  Top Layer w0.1: v1(78.125,33.2) 78.725,32.6 81.875,32.6 82.275,32.2 U1.8@82.665,32.2
  Signal Layer 4 w0.1: LCD1.8@56.4,23.8 57.275,24.675 60.975,24.675 61.575,24.075 67.425,24.075 76.55,33.2 v1(78.125,33.2)
LCD_CP: C40.1 U1.33 | length 1.3
  Top Layer w0.1: C40.1@89.7,33.8 C40.1@89.75,33.75
  Top Layer w0.2: U1.33@88.535,33.8 C40.1@89.7,33.8 ; C40.1@89.75,33.75 C40.1@89.85,33.75
LCD_D2: LCD1.11 U1.46 | length 31.1
  Top Layer w0.1: v1(82.075,36.75) 82.3,36.525 83.75,36.525 84.2,36.075 U1.46@84.2,35.735
  Signal Layer 3 w0.1: v1(74.475,44.825) 76.6,44.825 81.55,39.875 81.55,37.275 v1(82.075,36.75)
  Signal Layer 4 w0.1: LCD1.11@60.4,49.2 68.8,49.2 72.775,45.225 74.075,45.225 v1(74.475,44.825)
LCD_D3: LCD1.12 U1.45 | length 34.3
  Top Layer w0.1: v1(82.05,37.358) 82.05,37.3 82.1,37.3 82.675,36.725 83.949,36.725 84.6,36.074 U1.45@84.6,35.735
  Signal Layer 3 w0.1: v1(74.425,45.525) 76.475,45.525 82.05,39.95 v1(82.05,37.358)
  Signal Layer 4 w0.1: LCD1.12@58.4,49.2 59.325,50.125 68.375,50.125 72.975,45.525 v1(74.425,45.525)
LCD_D4: LCD1.13 U1.44 | length 36.9
  Top Layer w0.1: v1(82.825,37.15) 83.05,36.925 84.15,36.925 85,36.075 U1.44@85,35.735
  Signal Layer 3 w0.1: v1(74.413,46.175) 76.525,46.175 82.825,39.875 v1(82.825,37.15)
  Signal Layer 4 w0.1: LCD1.13@56.4,49.2 57.575,50.375 68.525,50.375 72.725,46.175 v1(74.413,46.175)
LCD_D5: LCD1.14 U1.43 | length 39.5
  Top Layer w0.1: v1(83.479,37.327) 83.681,37.125 84.35,37.125 85.4,36.075 U1.43@85.4,35.735
  Signal Layer 3 w0.1: v1(75.1,46.65) 76.65,46.65 83.479,39.821 v1(83.479,37.327)
  Signal Layer 4 w0.1: LCD1.14@54.4,49.2 55.9,50.7 68.7,50.7 72.75,46.65 v1(75.1,46.65)
LED_JLINK: LED901.2 TPJ912.1 U900.A7 | length 55.1
  Top Layer w0.1: U900.A7@48.5,38.5 48.5,38.364 48.357,38.221 48.357,37.062 48.543,36.876 48.543,36.082 48.407,35.946 48.407,35.393 48.925,34.875 48.925,33.575 v1(49.2,33.3)
  Top Layer w0.2: LED901.2@10.65,50.4 v1@11.25,50.4
  Signal Layer 4 w0.1: v1(11.45,50.4) 12.1,50.4 29.8,32.7 35.5,32.7 36.2,33.4 41.3,33.4 42.2,34.3 44.25,34.3 45.5,33.05 48.95,33.05 v1(49.2,33.3)
  Bottom Layer w0.1: v1(49.2,33.3) 50.5,33.3 50.751,33.551 TPJ912.1@50.751,34.225 TPJ912.1@50.751,34.343
LED_STATUS_G: LED904.3 U900.D13 | length 24
  Top Layer w0.1: v1(44.075,39.5) 44.075,39.582 44.675,40.182 45.182,40.182 45.314,40.05 45.45,40.05 U900.D13@45.5,40
  Top Layer w0.2: LED904.3@29.95,46.15 v1(30.65,46.15)
  Signal Layer 4 w0.1: v1(30.65,46.15) 30.475,46.15 29.15,44.825 29.15,41.85 30.75,40.25 42.65,40.25 42.875,40.475 43.775,40.475 44.075,40.175 v1(44.075,39.5)
LED_STATUS_R: LED904.4 U900.E13 | length 21.1
  Top Layer w0.1: v1(44.875,40.775) 45.225,40.775 U900.E13@45.5,40.5
  Top Layer w0.2: LED904.4@29.95,45.45 v1(30.65,45.45)
  Signal Layer 4 w0.1: v1(30.65,45.45) 29.55,44.35 29.55,42.175 30.125,41.6 30.6,41.125 44.525,41.125 v1(44.875,40.775)
LES_LC_SENSE: R126.1 R307.2 | length 31.1
  Top Layer w0.1: R307.2@48.7,8.55 v1(49.325,8.55) ; v1(78.35,9.6) R126.1@78.35,10.25
  Signal Layer 4 w0.1: v1(49.325,8.55) 49.775,8.1 76.85,8.1 v1(78.35,9.6)
LFXTAL_I: U1.47 X2.2 | length 3
  Top Layer w0.1: X2.2@81.275,36.45 81.4,36.325 83.549,36.325 83.8,36.074 U1.47@83.8,35.735
LFXTAL_O: U1.48 X2.1 | length 2.8
  Top Layer w0.1: X2.1@81.275,35.45 81.475,35.45 82.15,36.125 U1.48@83.425,36.125 ; U1.48@83.4,35.735 U1.48@83.4,36.1
MCU_B0: R304.1 R316.1 U1.22 | length 46.2
  Top Layer w0.1: R316.1@56.4,6.65 R304.1@56.4,7.65 v1(57.025,7.65) ; U1.22@87,29.865 87.018,29.847 87.018,28.482 v1(87.025,28.475)
  Signal Layer 3 w0.1: v1(57.025,7.65) 58.15,8.775 v1(58.15,16.325)
  Signal Layer 4 w0.1: v1(58.15,16.325) 59.425,17.6 68.25,17.6 75.325,24.675 83.45,24.675 87.025,28.25 v1(87.025,28.475)
MCU_B3: R307.1 R317.1 U1.19 | length 53.9
  Top Layer w0.1: R317.1@48.7,6.65 R307.1@48.7,7.65 v1(49.35,7.65) ; U1.19@85.8,29.865 85.8,29.05 v1(85.825,29.025)
  Signal Layer 3 w0.1: v1(49.35,7.65) 50,8.3 50,10.725 49.425,11.3 v1(49.425,16.675)
  Signal Layer 4 w0.1: v1(49.425,16.675) 51.325,18.575 67.875,18.575 74.825,25.525 82.975,25.525 85.718,28.268 85.718,28.918 v1(85.825,29.025)
N16768220: R104.1 SW100.1 SW100.2 | length 5.2
  Top Layer w0.1: R104.1@49.35,14.05 50.4,14.05 SW100.1@50.425,14.075 SW100.2@54.575,14.075
N16768338: R105.1 SW101.1 SW101.2 | length 5.2
  Top Layer w0.1: R105.1@37.35,14.05 38.4,14.05 SW101.1@38.425,14.075 SW101.2@42.575,14.075
N16769621: LED101.1 R107.1 | length 0.9
  Top Layer w0.3: LED101.1@62.5,13.45 63.15,13.45 R107.1@63.3,13.3
N16769748: LED100.1 R106.1 | length 0.9
  Top Layer w0.3: R106.1@66.7,13.3 67.35,13.3 LED100.1@67.5,13.45
N16771127: R111.2 U101.2 U101.4 U101.9 U101.10 | length 24.6
  Top Layer w0.2: U101.2@61,33.915 61,33.4 61.225,33.175 61.6,33.175 61.8,33.375 U101.4@61.8,33.915 61.8,34.35 61.725,34.425 61.725,35.175 ; U101.10@61.4,35.685 61.4,35.326 61.551,35.175 61.725,35.175 ; U101.9@61.8,35.685 61.8,35.25 61.725,35.175
  Top Layer w0.3: v1(60.7,32.3) 60.7,32.65 61.225,33.175 ; R111.2@72.5,35.85 72.85,36.2 v1(73.2,36.2)
  Signal Layer 4 w0.3: v1(60.7,32.3) 61.107,31.893 61.31,31.893 61.503,31.7 63.8,31.7 64.8,30.7 68.928,30.7 69.728,31.5 72.4,31.5 v1(72.8,31.9)
  Bottom Layer w0.3: v1(72.8,31.9) 72.4,32.3 72.4,35.4 v1(73.2,36.2)
N16772319: C124.1 L125.1 R122.2 | length 6.9
  Top Layer w0.1: R122.2@79.25,11.15 80.05,11.15 C124.1@80.1,11.2 82.537,11.2 83.837,12.5 L125.1@85.6,12.5
N16772327: C124.2 L125.2 R126.2 | length 7.1
  Top Layer w0.1: R126.2@79.25,10.25 80.05,10.25 C124.2@80.1,10.2 80.15,10.15 82.178,10.15 82.803,9.525 83.828,8.5 L125.2@85.6,8.5
N16772335: C123.1 R121.2 R122.1 | length 1.7
  Top Layer w0.1: R121.2@76.65,11.15 C123.1@77.5,11.15 R122.1@78.35,11.15
N16780374: C115.1 D101.1 R114.1 R116.2 | length 3.3
  Top Layer w0.3: C115.1@95.9,31.975 95.9,31.2 R114.1@95.85,31.15 D101.1@95.85,30 97.15,30 R116.2@97.175,30.025
N16780644: C110.1 R150.1 U102.5 | length 7.3
  Top Layer w0.3: R150.1@106.85,50.2 107.51,50.2 v1(107.535,50.175) ; U102.5@111.45,51.5 111.45,52.175 C110.1@111.525,52.25 ; C110.1@111.525,52.375 v1(112,52.375)
  Signal Layer 5 w0.3: v1(107.535,50.175) 109.8,50.175 v1(112,52.375)
N16808623: C127.1 P100.1 R120.2 R128.1 | length 7.9
  Top Layer w0.1: R128.1@104,9.7 C127.1@104,10.9 105.575,10.9 R120.2@105.6,10.925 110.625,10.925 P100.1@110.7,11
N16809528: D703.1 P700.1 Q703.3 ST701.2 | length 60.2
  Top Layer w0.5: ST701.2@2.875,4.62 3.82,4.62 v1@4.087,4.887 ; v1(4.087,4.981) v1@4.087,4.887 ; P700.1@7,6.078 5.278,6.078 v1@4.087,4.887 ; v1(10.046,4.981) 12.019,4.981 12.675,4.325 D703.1@13.2,4.325 14.525,4.325 14.8,4.6 Q703.3@14.8,5.325
  Top Layer w1: P700.1@5.947,5.025 P700.1@7,6.078
  Signal Layer 3 w0.6: v1(3.958,7.181) 3.958,4.988 3.962,4.984 3.962,4.981 v1(4.087,4.981) v1(10.046,4.981) v1(10.046,6.081) v1(10.046,7.181) 11.714,7.181 17.039,12.506 17.039,20.919 11.133,26.825 v1(10.046,26.825) v1(10.046,27.925) 10.046,29.025 v1(3.958,29.025) 3.958,29.023 3.962,29.019 v1(3.962,27.925) v1(3.962,26.825)
  other v1: 3.962,6.081
N16809565: Q703.2 SW704.6 TP156.1 | length 5.4
  Top Layer w0.5: Q703.2@15.3,3.65 Q703.2@15.325,3.625
  Top Layer w0.635: Q703.2@15.325,3.625 v1(15.8,3.625) 17.15,3.625 18.4,2.375 SW704.6@18.4,1.75
  Bottom Layer w0.3: TP156.1@15.3,4.6 15.8,4.1 v1(15.8,3.625)
N16809744: R793.1 SW704.1 | length 2.1
  Top Layer w0.1: SW704.1@23.4,7.25 23.4,8 R793.1@24.7,8
N16809746: R794.1 SW704.3 | length 2
  Top Layer w0.1: R794.1@17.1,7.95 18.4,7.95 SW704.3@18.4,7.25
N16811360: R7.2 SW1.3 SW1.4 | length 5.5
  Top Layer w0.1: R7.2@99.45,40.85 99.725,40.575 99.725,40.35 100.075,40 SW1.4@100.075,39.775 SW1.3@100.075,35.625
N16812963: Q703.1 R792.2 | length 0.8
  Top Layer w0.1: R792.2@14.275,2.9 14.3,2.925 Q703.1@14.3,3.65
N16814259: L1.2 R2.1 | length 1
  Top Layer w0.5: L1.2@83.19,39.55 83.95,39.55 R2.1@84.1,39.7
N16814326: C3.1 C4.1 R2.2 U1.41 | length 5.4
  Top Layer w0.2: U1.41@86.2,35.735 86.2,36.775 C4.1@86.275,36.85 86.324,36.85 86.635,37.161 86.635,37.79 86.425,38
  Top Layer w0.5: R2.2@84.1,38.8 84.1,38.65 84.425,38.325 C3.1@85.15,38.325 85.2,38.375 86.088,38.375 86.444,38.019
N16815537: C12.1 C13.1 C14.1 L11.2 U1.14 U1.40 | length 21.2
  Top Layer w0.2: U1.14@83.8,29.865 83.8,29.2 83.825,29.175 v1(83.825,29.075) ; U1.40@86.6,35.735 86.6,36.45 C13.1@87.025,36.875 C14.1@87.025,37.425 87.025,38.1 87.05,38.125
  Top Layer w0.5: 87.05,38.125 C12.1@87.05,38.825 ; C12.1@87.085,38.79 C12.1@87.05,38.825 ; L11.2@91.4,39.06 90.74,39.06 90.1,39.7 87.85,39.7 87.05,38.9 C12.1@87.05,38.825
  Signal Layer 3 w0.5: v1(83.825,29.075) 83.825,30.2 85.55,31.925 85.7,31.925 86.625,32.85 86.625,38.475 v1(87.625,39.475)
N16816128: L11.1 U1.37 | length 4.1
  Top Layer w0.2: U1.37@87.8,35.735 87.865,35.8 88.1,35.8 88.3,36 88.35,36
  Top Layer w0.5: 88.35,36 88.525,36.175 90.086,36.175 90.901,36.99 L11.1@91.4,36.99
N16831167: R700.1 U701.7 | length 0.9
  Top Layer w0.1: U701.7@40.15,26.75 40.15,25.925 R700.1@40.225,25.85
N16831188: C705.1 U701.6 | length 0.9
  Top Layer w0.1: U701.6@39.65,26.75 39.65,25.85 C705.1@39.675,25.825
N16831199: R702.1 R703.2 U701.5 | length 1.5
  Top Layer w0.1: R703.2@38.575,25.85 R702.1@39.125,25.85 39.15,25.875 U701.5@39.15,26.75
N16831281: R705.2 TP711.1 U702.11 | length 2.5
  Top Layer w0.1: v1(40.35,32.875) R705.2@40.875,33.4 41,33.275 U702.11@41.815,33.275
  Bottom Layer w0.1: v1(40.35,32.875) 40.35,32.1 TP711.1@40.375,32.075
N16831285: R706.2 TP712.1 U702.8 | length 2.6
  Top Layer w0.1: v1(40.55,34.8) 40.875,34.8 R706.2@41,34.675 41.2,34.475 U702.8@41.815,34.475
  Bottom Layer w0.1: TP712.1@39.7,34.4 40.1,34.8 v1(40.55,34.8) v1@40.45,34.9
N16831289: R707.2 TP713.1 U702.3 | length 3.1
  Top Layer w0.1: U702.3@43.585,33.675 44.35,33.675 R707.2@44.4,33.725 ; R707.2@44.45,33.725 R707.2@44.4,33.725 ; v1(44.975,34.725) 44.8,34.55 44.8,34.125 R707.2@44.4,33.725
  Bottom Layer w0.1: TP713.1@44.255,34.025 44.955,34.725 v1(44.975,34.725)
N16831309: R708.2 TP714.1 U702.1 | length 2.1
  Top Layer w0.1: v1(43.625,32.475) 43.625,32.5 43.585,32.54 U702.1@43.585,32.875 44.35,32.875 R708.2@44.4,32.925
  Bottom Layer w0.1: TP714.1@43.025,31.875 v1(43.625,32.475)
N16831821: C707.1 L702.2 U702.14 | length 1.9
  Top Layer w0.2: C707.1@42.85,31.975 42.9,32.025 U702.14@42.9,32.79
  Top Layer w0.3: L702.2@42.435,31.05 42.85,31.465 C707.1@42.85,31.975
N16835747: Q705.3 Q705.6 Q705.7 Q705.8 U700.3 | length 4.1
  Top Layer w0.6: U700.3@33.6,30.475 33.838,30.713 Q705.6@34.7,30.713 34.7,29.983 Q705.7@34.884,29.8 35.816,29.8 36,29.617 Q705.3@36,28.888
N16839091: R709.1 U703.1 U703.2 | length 3.3
  Top Layer w0.1: U703.2@39.05,36.05 39.625,36.05 39.75,35.925 39.75,35.725 39.575,35.55 U703.1@39.05,35.55 39.05,34.1 R709.1@39.15,34
N16839103: C710.2 U703.6 | length 0.8
  Top Layer w0.25: C710.2@35.45,36.575 35.475,36.55 U703.6@36.25,36.55
N16839111: C729.1 R718.2 U703.4 U704.3 U704.5 | length 9.5
  Top Layer w0.1: U704.3@34.345,40.675 35.8,40.675 36.45,40.025 U704.5@38.4,40.025 ; U704.5@38.556,40.025 U704.5@38.4,40.025 ; U703.4@39.025,37.075 U703.4@39.05,37.05 ; R718.2@40.725,37.325 40.1,37.325 C729.1@39.825,37.05 U703.4@39.05,37.05 ; U704.5@38.4,40.025 38.4,38.4 39.05,37.75 U703.4@39.05,37.05
N16839131: R710.1 U703.8 | length 2.6
  Top Layer w0.1: U703.8@36.25,35.55 36.25,35.175 36.575,34.85 37.1,34.85 R710.1@37.95,34
N16839143: L700.2 R717.1 | length 1
  Top Layer w0.5: L700.2@33.45,33.9 R717.1@34.4,33.9
N16839420: C766.1 R765.1 R767.2 U704.2 | length 3.1
  Top Layer w0.1: R767.2@32.6,39.55 R765.1@32.6,40.6 33.025,41.025 C766.1@33.5,41.025 33.8,41.325 U704.2@34.345,41.325
N16839426: C766.2 R764.1 R765.2 U704.1 | length 3.6
  Top Layer w0.1: R764.1@32.525,43.275 32.525,42.075 R765.2@32.6,42 33.025,41.575 C766.2@33.5,41.575 33.5,41.9 33.575,41.975 U704.1@34.345,41.975
N16839472: C770.1 R769.1 R771.2 U704.6 | length 3.5
  Top Layer w0.1: U704.6@38.556,40.675 39.275,40.675 C770.1@39.4,40.8 39.7,40.5 39.9,40.5 R769.1@40.3,40.1 40,39.8 40,39.4 R771.2@39.6,39
N16839478: C770.2 R768.1 R769.2 U704.7 | length 2.8
  Top Layer w0.1: U704.7@38.556,41.325 38.581,41.35 C770.2@39.4,41.35 40.15,41.35 R769.2@40.3,41.5 R768.1@40.3,42.5
N16839586: C730.1 C731.1 R731.1 U704.8 | length 3.9
  Top Layer w0.5: R731.1@37.05,44.9 37.525,44.9 38.5,43.925 C731.1@38.5,43.8 38.555,43.745 38.555,42.031 38.5,42.031 U704.8@38.556,41.975
N16839602: L704.2 R731.2 | length 0.9
  Top Layer w0.5: L704.2@36.075,45.8 36.075,44.975 R731.2@36.15,44.9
